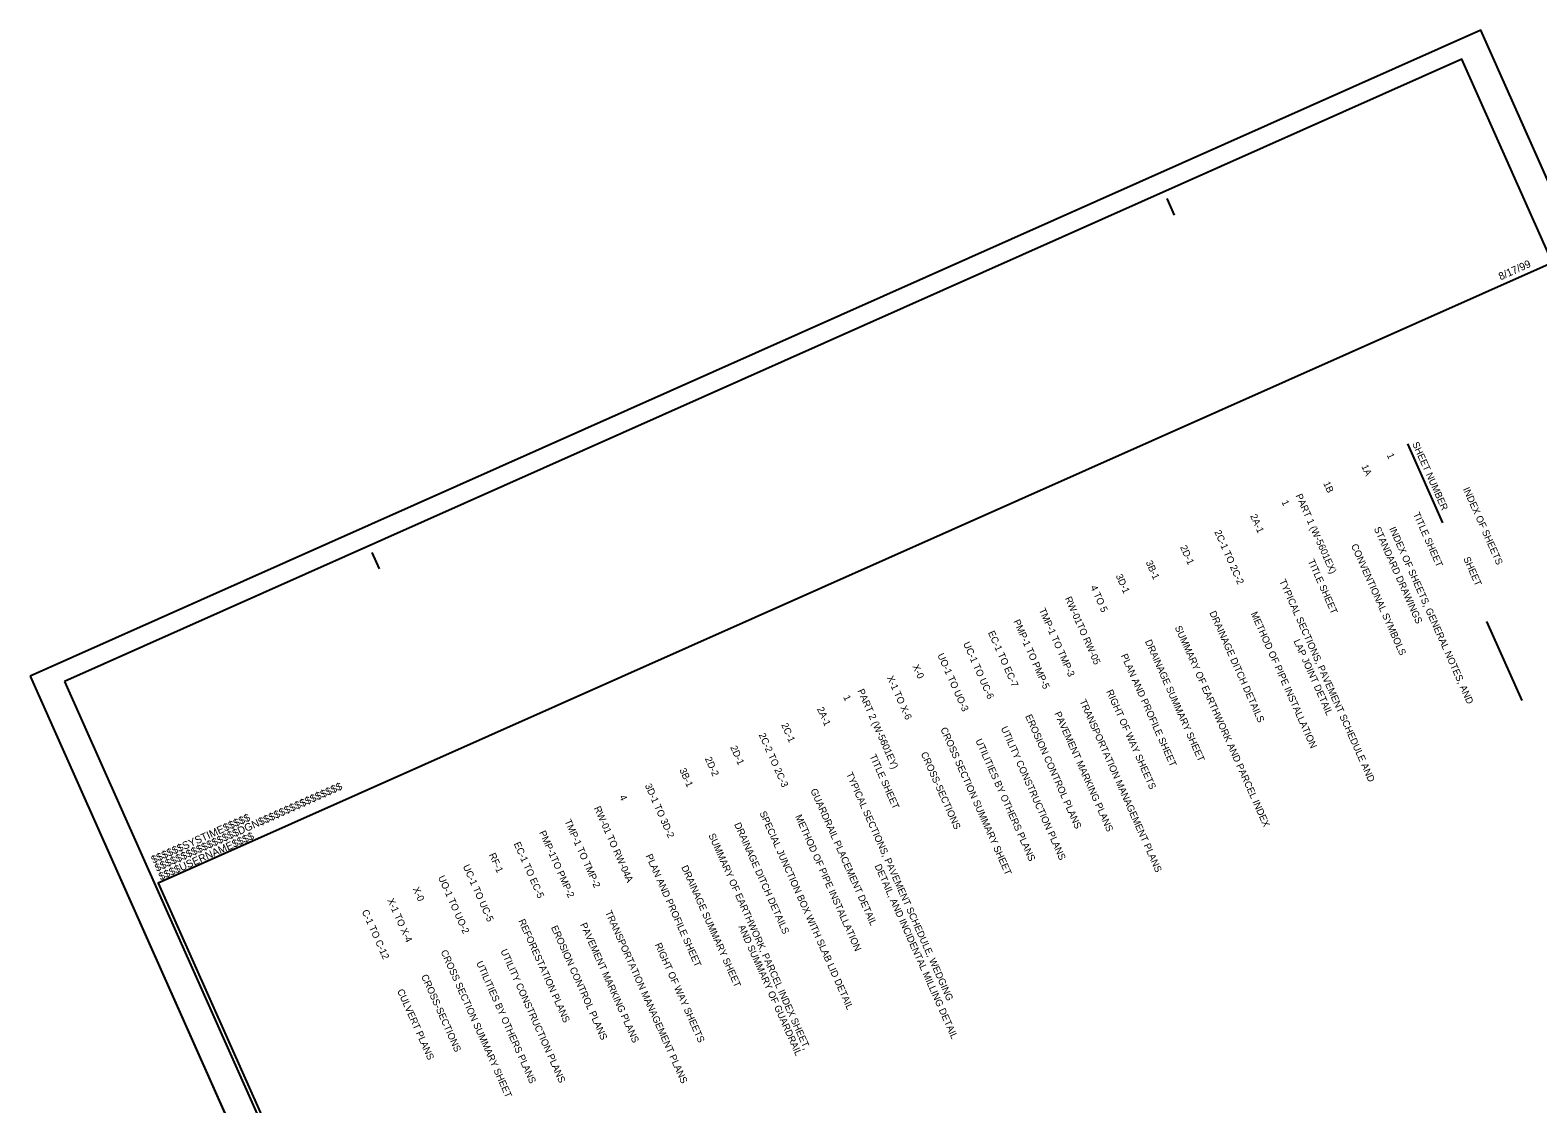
# Model space of a CAD drawing. Extents: x 885268 to 886953, y 552794 to 554777.
# Drawn here: x 885268 to 886308, y 554037 to 554777 of the extents above; entities that cross this region are included whole.
import ezdxf

# ---------------------------------------------------------------- set-up
doc = ezdxf.new("R2010")
doc.units = 0
for name, color, linetype in [('Sheet Cutting Line CELL', 7, 'Continuous'), ('Sheet Data Text CELL', 7, 'Continuous'), ('Sheet Plan CELL', 7, 'Continuous'), ('Sheet Plot Border Inside CELL', 7, 'Continuous'), ('Sheet Plot Border Outside CELL', 7, 'Continuous')]:
    doc.layers.add(name, color=color, linetype=linetype)

msp = doc.modelspace()

# ---------------------------------------------------------------- linework, layer by layer
at = {"layer": 'Sheet Cutting Line CELL'}
for p, q in [((886268.4, 554777.5), (885268.1, 554332)), ((886953.3, 553239.6), (886268.4, 554777.5)), ((885268.1, 554332), (885953, 552794.1))]:
    msp.add_line(p, q, dxfattribs=at)
at = {"layer": 'Sheet Data Text CELL'}
for p, q in [((886217.8, 554492.3), (886242.1, 554437.7)), ((886272.4, 554369.7), (886296.7, 554315.1))]:
    msp.add_line(p, q, dxfattribs=at)
at = {"layer": 'Sheet Plan CELL'}
for p, q in [((886051.9, 554661.4), (886057, 554650)), ((885503.8, 554417.3), (885508.9, 554405.9)), ((885356.4, 554189.1), (885356.4, 554189.1))]:
    msp.add_line(p, q, dxfattribs=at)
msp.add_lwpolyline([(886925.8, 553246), (886315.6, 554616.2), (885356.4, 554189.1), (885966.6, 552818.8)], close=True, dxfattribs=at)
at = {"layer": 'Sheet Plot Border Inside CELL'}
msp.add_lwpolyline([(885291.7, 554328.3), (885969.4, 552806.4), (886933.2, 553235.6), (886255.4, 554757.5)], close=True, dxfattribs=at)
at = {"layer": 'Sheet Plot Border Outside CELL'}
msp.add_lwpolyline([(885268.1, 554332), (885953, 552794.1), (886953.3, 553239.6), (886268.4, 554777.5)], close=True, dxfattribs=at)

# ---------------------------------------------------------------- texts
at = {"layer": 'Sheet Data Text CELL'}
for s, p in [('SHEET NUMBER                    SHEET   ', (886221, 554492.3)), ('1                       TITLE SHEET', (886203.5, 554484.5)), ('1A                      INDEX OF SHEETS, GENERAL NOTES, AND ', (886186, 554476.7)), ('1B                      CONVENTIONAL SYMBOLS ', (886159.7, 554465)), ('                        INDEX OF SHEETS ', (886238.6, 554500.1)), ('1                       TITLE SHEET', (886130.9, 554452.1)), ('PART 1 (W-5601EX)', (886140.6, 554456.5)), ('2A-1                    TYPICAL SECTIONS, PAVEMENT SCHEDULE AND ', (886109.3, 554442.5)), ('2C-1 TO 2C-2            METHOD OF PIPE INSTALLATION', (886084.6, 554431.5)), ('                        STANDARD DRAWINGS', (886177.2, 554472.8)), ('2D-1                    DRAINAGE DITCH DETAILS', (886061, 554421)), ('3B-1                    SUMMARY OF EARTHWORK AND PARCEL INDEX', (886037.3, 554410.5)), ('3D-1                    DRAINAGE SUMMARY SHEET', (886016.6, 554401.2)), ('RW-01TO RW-05           RIGHT OF WAY SHEETS', (885981.5, 554385.6)), ('4 TO 5                  PLAN AND PROFILE SHEET', (885999.1, 554393.4)), ('TMP-1 TO TMP-3          TRANSPORTATION MANAGEMENT PLANS', (885963.6, 554377.6)), ('PMP-1 TO PMP-5          PAVEMENT MARKING PLANS', (885946, 554369.8)), ('UC-1 TO UC-6            UTILITY CONSTRUCTION PLANS', (885911.4, 554354.4)), ('EC-1 TO EC-7            EROSION CONTROL PLANS', (885928.5, 554362)), ('        LAP JOINT DETAIL ', (886133.4, 554369.2)), ('UO-1 TO UO-3            UTILITIES BY OTHERS PLANS', (885893.6, 554346.5)), ('X-0                     CROSS SECTION SUMMARY SHEET', (885876.4, 554338.8)), ('X-1 TO X-6              CROSS-SECTIONS', (885858.8, 554331)), ('1                       TITLE SHEET', (885828.7, 554317.6)), ('PART 2 (W-5601EY)', (885838.5, 554321.9)), ('2A-1                    TYPICAL SECTIONS, PAVEMENT SCHEDULE, WEDGING', (885810.6, 554309.5)), ('2C-2 TO 2C-3            METHOD OF PIPE INSTALLATION', (885770.4, 554291.6)), ('2C-1                    GUARDRAIL PLACEMENT DETAIL', (885785.9, 554298.5)), ('2D-1                    SPECIAL JUNCTION BOX WITH SLAB LID DETAIL ', (885750.8, 554282.9)), ('2D-2                    DRAINAGE DITCH DETAILS', (885733.3, 554275.1)), ('3B-1                    SUMMARY OF EARTHWORK, PARCEL INDEX SHEET,', (885715.7, 554267.3)), ('3D-1 TO 3D-2            DRAINAGE SUMMARY SHEET', (885691.9, 554256.6)), ('RW-01 TO RW-04A  ', (885656.8, 554241)), ('4                       PLAN AND PROFILE SHEET', (885674.3, 554248.8)), ('TMP-1 TO TMP-2          TRANSPORTATION MANAGEMENT PLANS', (885636.5, 554232)), ('PMP-1TO PMP-2           PAVEMENT MARKING PLANS', (885619, 554224.2)), ('RF-1                    REFORESTATION PLANS', (885584.4, 554208.8)), ('EC-1 TO EC-5            EROSION CONTROL PLANS', (885601.5, 554216.4)), ('UC-1 TO UC-5            UTILITY CONSTRUCTION PLANS', (885566.4, 554200.8)), ('DETAIL, AND INCIDENTAL MILLING DETAIL ', (885850.3, 554201.1)), ('UO-1 TO UO-2            UTILITIES BY OTHERS PLANS', (885549.3, 554193.2)), ('X-1 TO X-4              CROSS-SECTIONS', (885514.3, 554177.5)), ('X-0                     CROSS SECTION SUMMARY SHEET', (885531.8, 554185.3)), ('C-1 TO C-12             CULVERT PLANS', (885496.7, 554169.7)), ('AND SUMMARY OF GUARDRAIL', (885756.3, 554159.2)), ('    RIGHT OF WAY SHEETS', (885695.9, 554153.3))]:
    msp.add_text(s, height=4.8, rotation=294.0046, dxfattribs=at).set_placement(p)
at = {"layer": 'Sheet Plan CELL'}
for s, p in [('8/17/99', (886282.1, 554604.9)), ('$$$$$$$$$$$$$$$$DGN$$$$$$$$$$$$$$$$', (885355.5, 554197)), ('$$$$$$SYSTIME$$$$$', (885353, 554202.6)), ('$$$$USERNAME$$$$', (885358.1, 554191))]:
    msp.add_text(s, height=5.25, rotation=24.0046, dxfattribs=at).set_placement(p)

doc.saveas('drawing.dxf')
